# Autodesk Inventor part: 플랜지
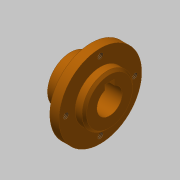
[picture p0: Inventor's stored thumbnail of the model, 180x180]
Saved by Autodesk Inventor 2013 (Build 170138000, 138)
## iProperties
Created: 2019-10
Part Number: 플랜지
Material: 스테인리스강
Document SubType Name: Modeling
Designer: mduedu
Density: 1 g/cm^3
Author: mduedu
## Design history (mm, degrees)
sketch "스케치1"
  geometry: L1 (0, 0)-(9, 0); L2 (9, 0)-(9, 10); L3 (9, 10)-(0, 10); L4 (0, 10)-(0, 0); L5 (9, 0)-(13, 0); L6 (13, 0)-(13, 18); L7 (13, 18)-(9, 18); L8 (9, 18)-(9, 0); L9 (13, 0)-(17, 0); L10 (17, 0)-(17, 11); L11 (17, 11)-(13, 11); L12 (13, 11)-(13, 0)
  constraints: 24 end point, 6 parallel, 3 horizontal, 3 perpendicular
  dimensions: "d0" = 17 distance between parallel lines of L10 L4; "d2" = 20 diameter of L3 L1; "d3" = 22 diameter of L11 L9; "d4" = 36 diameter of L7 L5; "d5" = 4 distance of L6.end L7.end; "d6" = 4 distance of L10.end L11.end
revolve "회전1" sketch "스케치1" stored, may be unused: angle "d7" = 90 deg
sketch "스케치2"
  geometry: L1 (-2, 5.123)-(2, 5.123); L2 (2, 5.123)-(2, 7.3); L3 (2, 7.3)-(-2, 7.3); L4 (-2, 7.3)-(-2, 5.123); A1 r 5.5 centre (0, 0) between (-2, 5.123) and (2, 5.123); 1 further point
  constraints: 8 end point, 2 parallel, 2 point on circle, 1 centre point, 1 coincident, 1 horizontal, 1 perpendicular
  dimensions: "d8" = 11 diameter of A1; "d10" = 4 distance of L2.end L3.end; "d11" = 7.3 distance from line of L3 point (0, 0)
extrude "돌출1" cut sketch "스케치2" stored distance "d12" = 10; taper "d13" = 0 deg
chamfer "모따기1" distance "d14" = 1; stored, may be unused: second distance "d15" = 2, angle "d16" = 45 deg
chamfer "모따기2" distance "d17" = 1; stored, may be unused: second distance "d18" = 2, angle "d19" = 45 deg
sketch "스케치3" dims "d20" = 30
  geometry: 3 further points
  constraints: 2 vertical alignment, 1 coincident, 2 other
hole "구멍1" sketch "스케치3" at (0, 15) diameter "d21" = 2.459; stored, may be unused: countersink angle "d25" = 90 deg, drill point angle "d27" = 118 deg; dims "d22" = 6, "d23" = 4, "d24" = 2, "d26" = 8
node "솔리드1"
pattern_circular "원형 패턴1" dims angle "d29" = 360 deg
